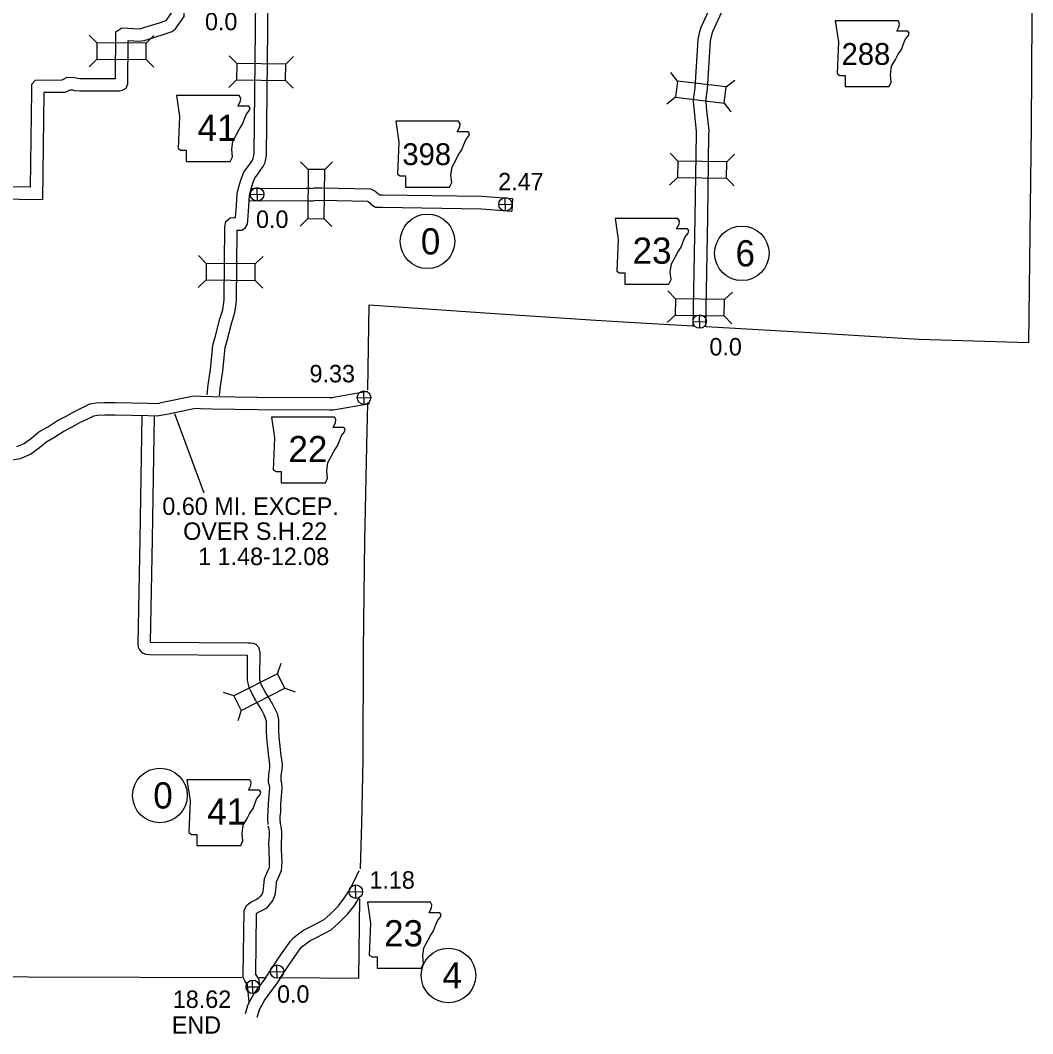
# Model space of a CAD drawing. Extents: x -939622 to -934245, y 1383184 to 1385301.
# Drawn here: x -936241.4 to -936167.9, y 1384497 to 1384570.6 of the extents above; entities that cross this region are included whole.
import ezdxf

# ---------------------------------------------------------------- set-up
doc = ezdxf.new("R2010")
doc.units = 0
for name, color, linetype in [('Level 10', 7, 'Continuous'), ('Level 2', 7, 'Continuous'), ('Level 20', 7, 'Continuous'), ('Level 21', 7, 'Continuous'), ('Level 25', 7, 'Continuous'), ('Level 26', 7, 'Continuous'), ('Level 27', 7, 'Continuous')]:
    doc.layers.add(name, color=color, linetype=linetype)

msp = doc.modelspace()

# ---------------------------------------------------------------- linework, layer by layer
at = {"layer": 'Level 10'}
for points in [[(-936192.57, 1384548.379), (-936192.426, 1384556.309), (-936192.345, 1384562.392), (-936192.332, 1384562.573), (-936192.503, 1384564.235), (-936192.549, 1384564.725), (-936192.522, 1384565.044), (-936192.44, 1384565.717), (-936192.226, 1384569.222), (-936192.094, 1384569.796), (-936192.004, 1384570.12), (-936190.111, 1384574.267), (-936189.791, 1384574.975), (-936189.482, 1384575.491), (-936189.193, 1384575.881), (-936188.85, 1384576.217), (-936187.072, 1384577.94), (-936186.895, 1384578.191), (-936186.701, 1384578.477), (-936186.578, 1384578.75), (-936186.455, 1384579.037), (-936186.424, 1384579.288), (-936186.351, 1384579.71), (-936186.114, 1384581.082)], [(-936191.67, 1384548.363), (-936191.526, 1384556.295), (-936191.445, 1384562.355), (-936191.429, 1384562.588), (-936191.607, 1384564.324), (-936191.646, 1384564.729), (-936191.626, 1384564.951), (-936191.543, 1384565.635), (-936191.332, 1384569.092), (-936191.221, 1384569.575), (-936191.156, 1384569.811), (-936189.292, 1384573.894), (-936188.992, 1384574.557), (-936188.733, 1384574.991), (-936188.513, 1384575.287), (-936188.222, 1384575.572), (-936186.385, 1384577.352), (-936186.155, 1384577.679), (-936185.912, 1384578.037), (-936185.754, 1384578.389), (-936185.578, 1384578.799), (-936185.533, 1384579.155), (-936185.464, 1384579.556), (-936185.227, 1384580.929)], [(-936240.303, 1384566.283), (-936238.366, 1384566.303), (-936238.286, 1384566.34), (-936238.002, 1384566.484), (-936237.455, 1384566.471), (-936237.275, 1384566.408), (-936237.092, 1384566.397), (-936236.707, 1384566.395), (-936234.498, 1384566.389), (-936234.485, 1384569.777), (-936234.058, 1384570.069), (-936233.602, 1384570.059), (-936232.794, 1384570), (-936232.64, 1384570.024), (-936232.442, 1384570.087), (-936231.246, 1384570.458), (-936230.822, 1384570.609), (-936230.802, 1384570.624), (-936230.41, 1384571.192), (-936230.353, 1384572.883)], [(-936227.862, 1384543.422), (-936227.771, 1384544.166), (-936227.613, 1384545.261), (-936227.524, 1384546.227), (-936227.435, 1384547.038), (-936227.275, 1384547.615), (-936226.935, 1384548.938), (-936226.72, 1384549.608), (-936226.635, 1384550.129), (-936226.621, 1384550.33), (-936226.563, 1384555.629), (-936226.505, 1384556.015), (-936226.18, 1384556.268), (-936225.926, 1384556.296), (-936225.801, 1384556.294), (-936225.734, 1384557.165), (-936225.676, 1384558.063), (-936225.526, 1384558.622), (-936225.392, 1384559.094), (-936225.183, 1384559.602), (-936224.908, 1384559.97), (-936224.719, 1384560.244), (-936224.563, 1384560.473), (-936224.503, 1384560.584), (-936224.448, 1384560.915), (-936224.325, 1384572.222)], [(-936226.963, 1384543.357), (-936226.879, 1384544.047), (-936226.719, 1384545.155), (-936226.628, 1384546.137), (-936226.548, 1384546.867), (-936226.405, 1384547.382), (-936226.07, 1384548.689), (-936225.843, 1384549.396), (-936225.74, 1384550.025), (-936225.721, 1384550.293), (-936225.665, 1384555.392), (-936225.33, 1384555.386), (-936225.09, 1384555.558), (-936224.923, 1384555.824), (-936224.913, 1384556.097), (-936224.837, 1384557.101), (-936224.783, 1384557.916), (-936224.659, 1384558.382), (-936224.54, 1384558.798), (-936224.394, 1384559.155), (-936224.177, 1384559.445), (-936223.976, 1384559.736), (-936223.794, 1384560.005), (-936223.64, 1384560.288), (-936223.549, 1384560.836), (-936223.425, 1384572.217)], [(-936239.716, 1384565.389), (-936238.163, 1384565.405), (-936237.892, 1384565.53), (-936237.796, 1384565.579), (-936237.618, 1384565.575), (-936237.455, 1384565.518), (-936237.122, 1384565.497), (-936236.71, 1384565.495), (-936234.191, 1384565.489), (-936234.017, 1384565.543), (-936233.743, 1384565.682), (-936233.6, 1384566.006), (-936233.587, 1384569.156), (-936232.757, 1384569.095), (-936232.432, 1384569.145), (-936232.172, 1384569.229), (-936230.962, 1384569.604), (-936230.388, 1384569.808), (-936230.142, 1384569.995), (-936229.519, 1384570.898), (-936229.484, 1384571.946)], [(-936240.303, 1384566.283), (-936240.596, 1384565.961), (-936240.614, 1384565.479), (-936240.704, 1384558.507), (-936248.42, 1384558.598), (-936253.269, 1384558.631)], [(-936239.716, 1384565.384), (-936239.816, 1384557.596), (-936248.429, 1384557.698), (-936253.276, 1384557.731)], [(-936224.612, 1384558.427), (-936224.067, 1384558.416), (-936220.672, 1384558.433), (-936220.333, 1384558.423), (-936220.245, 1384558.413), (-936220.084, 1384558.451), (-936219.804, 1384558.449), (-936219.549, 1384558.45), (-936216.01, 1384558.376), (-936215.663, 1384558.215), (-936215.424, 1384558.012), (-936215.383, 1384557.969), (-936215.365, 1384557.957), (-936215.144, 1384557.957), (-936207.908, 1384557.84), (-936205.682, 1384557.672), (-936205.749, 1384556.774)], [(-936224.77, 1384557.53), (-936224.074, 1384557.516), (-936220.683, 1384557.533), (-936220.393, 1384557.524), (-936220.188, 1384557.503), (-936219.984, 1384557.55), (-936219.804, 1384557.548), (-936219.556, 1384557.55), (-936216.217, 1384557.48), (-936216.153, 1384557.45), (-936216.045, 1384557.359), (-936215.964, 1384557.273), (-936215.63, 1384557.057), (-936215.151, 1384557.057), (-936207.949, 1384556.94), (-936205.749, 1384556.774)], [(-936241.655, 1384539.668), (-936241.131, 1384539.908), (-936240.582, 1384540.305), (-936240.07, 1384540.746), (-936239.45, 1384541.094), (-936238.706, 1384541.568), (-936238.079, 1384541.89), (-936237.523, 1384542.207), (-936236.912, 1384542.5), (-936236.365, 1384542.784), (-936235.901, 1384542.853), (-936235.296, 1384542.88), (-936234.541, 1384542.87), (-936232.136, 1384542.823), (-936231.562, 1384542.8), (-936231.364, 1384542.829), (-936230.977, 1384542.912), (-936228.944, 1384543.33), (-936228.644, 1384543.354), (-936228.302, 1384543.331), (-936227.468, 1384543.32), (-936224.199, 1384543.254), (-936219.006, 1384543.241), (-936218.778, 1384543.247), (-936218.425, 1384543.298), (-936216.203, 1384543.691)], [(-936242.279, 1384538.658), (-936241.392, 1384538.799), (-936240.675, 1384539.127), (-936240.024, 1384539.599), (-936239.552, 1384540.005), (-936238.987, 1384540.321), (-936238.257, 1384540.786), (-936237.65, 1384541.099), (-936237.104, 1384541.409), (-936236.51, 1384541.695), (-936236.084, 1384541.916), (-936235.814, 1384541.956), (-936235.282, 1384541.98), (-936234.557, 1384541.97), (-936232.163, 1384541.923), (-936231.514, 1384541.897), (-936231.204, 1384541.943), (-936230.792, 1384542.031), (-936228.816, 1384542.437), (-936228.638, 1384542.451), (-936228.338, 1384542.432), (-936227.483, 1384542.42), (-936224.209, 1384542.354), (-936218.994, 1384542.341), (-936218.701, 1384542.349), (-936218.283, 1384542.409), (-936216.046, 1384542.805)], [(-936232.605, 1384541.932), (-936232.644, 1384538.957), (-936232.747, 1384532.938), (-936232.885, 1384525.35), (-936232.868, 1384525.111), (-936232.755, 1384524.924), (-936232.606, 1384524.733), (-936232.334, 1384524.61), (-936232.033, 1384524.581), (-936224.939, 1384524.52), (-936224.961, 1384522.932), (-936224.957, 1384522.817), (-936224.946, 1384522.692), (-936224.932, 1384522.603), (-936224.912, 1384522.498), (-936224.888, 1384522.392), (-936224.859, 1384522.295), (-936224.823, 1384522.183), (-936224.788, 1384522.086), (-936224.736, 1384521.98), (-936224.501, 1384521.54), (-936224.436, 1384521.41), (-936224.354, 1384521.261), (-936224.261, 1384521.113), (-936224.054, 1384520.787), (-936223.967, 1384520.645), (-936223.929, 1384520.58), (-936223.893, 1384520.512)], [(-936231.706, 1384541.869), (-936231.744, 1384538.944), (-936231.847, 1384532.922), (-936231.983, 1384525.481), (-936224.912, 1384525.42), (-936224.717, 1384525.427), (-936224.524, 1384525.401), (-936224.326, 1384525.327), (-936224.131, 1384525.102), (-936224.045, 1384524.856), (-936224.036, 1384524.709), (-936224.061, 1384522.942), (-936224.058, 1384522.871), (-936224.052, 1384522.8), (-936224.046, 1384522.759), (-936224.031, 1384522.684), (-936224.016, 1384522.619), (-936223.999, 1384522.558), (-936223.972, 1384522.474), (-936223.959, 1384522.439), (-936223.934, 1384522.388), (-936223.702, 1384521.953), (-936223.64, 1384521.829), (-936223.579, 1384521.718), (-936223.5, 1384521.593), (-936223.291, 1384521.263), (-936223.197, 1384521.111), (-936223.144, 1384521.021), (-936223.097, 1384520.932)], [(-936223.097, 1384520.932), (-936222.943, 1384520.627), (-936222.771, 1384520.286), (-936222.683, 1384519.825), (-936222.665, 1384519.053), (-936222.648, 1384518.572), (-936222.5, 1384517.258), (-936222.414, 1384516.626), (-936222.439, 1384516.218), (-936222.511, 1384515.8), (-936222.518, 1384515.428), (-936222.469, 1384515.253), (-936222.427, 1384514.909), (-936222.45, 1384514.593), (-936222.527, 1384513.683), (-936222.541, 1384513.128), (-936222.574, 1384512.827), (-936222.574, 1384512.71), (-936222.557, 1384512.277)], [(-936223.893, 1384520.512), (-936223.747, 1384520.222), (-936223.632, 1384519.993), (-936223.581, 1384519.73), (-936223.565, 1384519.026), (-936223.546, 1384518.505), (-936223.393, 1384517.147), (-936223.318, 1384516.593), (-936223.335, 1384516.321), (-936223.409, 1384515.885), (-936223.42, 1384515.313), (-936223.354, 1384515.077), (-936223.331, 1384514.887), (-936223.347, 1384514.662), (-936223.426, 1384513.732), (-936223.44, 1384513.188), (-936223.474, 1384512.876), (-936223.474, 1384512.692), (-936223.456, 1384512.241)], [(-936223.441, 1384512.141), (-936223.382, 1384511.925), (-936223.351, 1384511.679), (-936223.353, 1384511.428), (-936223.394, 1384510.915), (-936223.372, 1384510.365), (-936223.344, 1384509.517), (-936223.352, 1384509.214), (-936223.359, 1384509.104), (-936223.453, 1384508.902), (-936223.718, 1384508.286), (-936223.74, 1384508.025), (-936223.778, 1384507.591), (-936223.816, 1384507.344), (-936223.871, 1384507.204), (-936224.042, 1384506.989), (-936224.143, 1384506.87), (-936224.275, 1384506.793), (-936224.604, 1384506.634), (-936224.865, 1384506.46), (-936225.025, 1384506.306), (-936225.184, 1384506.003), (-936225.253, 1384501.336), (-936225.257, 1384501.18)], [(-936222.572, 1384512.377), (-936222.497, 1384512.1), (-936222.45, 1384511.731), (-936222.454, 1384511.388), (-936222.493, 1384510.897), (-936222.473, 1384510.398), (-936222.444, 1384509.521), (-936222.453, 1384509.175), (-936222.471, 1384508.877), (-936222.632, 1384508.534), (-936222.834, 1384508.064), (-936222.844, 1384507.947), (-936222.884, 1384507.483), (-936222.942, 1384507.109), (-936223.083, 1384506.749), (-936223.346, 1384506.418), (-936223.555, 1384506.172), (-936223.851, 1384505.998), (-936224.157, 1384505.85), (-936224.287, 1384505.764), (-936224.352, 1384501.392)], [(-936223.603, 1384501.124), (-936222.621, 1384502.618), (-936221.81, 1384503.766), (-936221.573, 1384504.046), (-936221.318, 1384504.237), (-936220.85, 1384504.559), (-936220.329, 1384504.823), (-936219.825, 1384505.095), (-936219.367, 1384505.331), (-936218.924, 1384505.741), (-936218.323, 1384506.344), (-936217.901, 1384506.879), (-936217.53, 1384507.475), (-936217.191, 1384508.115), (-936216.816, 1384508.903)], [(-936222.499, 1384501.166), (-936221.877, 1384502.111), (-936221.098, 1384503.214), (-936220.952, 1384503.387), (-936220.793, 1384503.506), (-936220.39, 1384503.783), (-936219.912, 1384504.026), (-936219.405, 1384504.299), (-936218.846, 1384504.588), (-936218.3, 1384505.093), (-936217.649, 1384505.745), (-936217.163, 1384506.361), (-936216.812, 1384506.925)], [(-936224.029, 1384500.57), (-936224.045, 1384500.737), (-936224.088, 1384500.95), (-936224.141, 1384501.101), (-936224.352, 1384501.392)], [(-936224.816, 1384499.349), (-936224.936, 1384500.603), (-936224.952, 1384500.681), (-936224.989, 1384500.715), (-936225.119, 1384500.887), (-936225.257, 1384501.18)], [(-936223.603, 1384501.124), (-936224.425, 1384500.031), (-936224.594, 1384499.724), (-936224.792, 1384499.39), (-936224.929, 1384499.085), (-936225.104, 1384498.497)], [(-936222.499, 1384501.166), (-936222.721, 1384500.829), (-936223.665, 1384499.545), (-936223.813, 1384499.278), (-936223.992, 1384498.975), (-936224.084, 1384498.77), (-936224.241, 1384498.24)]]:
    msp.add_lwpolyline(points, dxfattribs=at)
at = {"layer": 'Level 2'}
for points in [[(-936191.637, 1384548.388), (-936184.086, 1384547.961), (-936176.198, 1384547.476), (-936168.21, 1384547.235), (-936168.129, 1384555.108), (-936168.033, 1384562.891), (-936167.971, 1384570.876), (-936167.936, 1384573.889)], [(-936216.185, 1384543.783), (-936216.091, 1384549.955), (-936208.041, 1384549.415), (-936200.041, 1384548.882), (-936197.253, 1384548.705)], [(-936197.253, 1384548.705), (-936192.59, 1384548.442)], [(-936216.628, 1384512.331), (-936216.542, 1384516.953), (-936216.499, 1384524.936), (-936216.407, 1384532.863), (-936216.229, 1384540.842), (-936216.2, 1384542.769)], [(-936216.733, 1384509.01), (-936216.733, 1384509.018), (-936216.628, 1384512.331)], [(-936222.469, 1384501.121), (-936216.846, 1384501.072), (-936216.764, 1384506.858)], [(-936245.302, 1384501.288), (-936240.826, 1384501.184), (-936232.764, 1384501.166), (-936225.326, 1384501.136)], [(-936224.068, 1384501.131), (-936223.692, 1384501.13)]]:
    msp.add_lwpolyline(points, dxfattribs=at)
at = {"layer": 'Level 20'}
for p, q in [((-936235.85, 1384568.982), (-936236.408, 1384569.544)), ((-936232.286, 1384568.967), (-936231.724, 1384569.525)), ((-936235.855, 1384567.794), (-936236.418, 1384567.236)), ((-936232.291, 1384567.779), (-936231.734, 1384567.217)), ((-936225.709, 1384567.476), (-936226.262, 1384568.043)), ((-936222.145, 1384567.437), (-936221.579, 1384567.991)), ((-936225.722, 1384566.289), (-936226.288, 1384565.735)), ((-936222.158, 1384566.25), (-936221.604, 1384565.683)), ((-936193.722, 1384566.208), (-936194.21, 1384566.832)), ((-936190.184, 1384565.777), (-936189.56, 1384566.266)), ((-936193.865, 1384565.029), (-936194.489, 1384564.54)), ((-936190.328, 1384564.598), (-936189.839, 1384563.974)), ((-936220.512, 1384559.786), (-936221.068, 1384560.35)), ((-936219.324, 1384559.777), (-936218.76, 1384560.332)), ((-936193.704, 1384560.397), (-936194.256, 1384560.965)), ((-936190.14, 1384560.349), (-936189.573, 1384560.902)), ((-936193.72, 1384559.209), (-936194.287, 1384558.657)), ((-936190.156, 1384559.162), (-936189.603, 1384558.594)), ((-936220.54, 1384556.222), (-936221.104, 1384555.667)), ((-936219.352, 1384556.213), (-936218.796, 1384555.649)), ((-936227.924, 1384552.968), (-936228.478, 1384553.534)), ((-936224.36, 1384552.929), (-936223.794, 1384553.483)), ((-936227.937, 1384551.78), (-936228.503, 1384551.226)), ((-936224.373, 1384551.741), (-936223.819, 1384551.175)), ((-936193.865, 1384550.408), (-936194.415, 1384550.978)), ((-936190.302, 1384550.344), (-936189.732, 1384550.894)), ((-936193.887, 1384549.221), (-936194.457, 1384548.671)), ((-936190.323, 1384549.156), (-936189.773, 1384548.586)), ((-936222.74, 1384523.187), (-936222.492, 1384523.939)), ((-936222.206, 1384522.126), (-936221.454, 1384521.878)), ((-936225.923, 1384521.583), (-936226.675, 1384521.832)), ((-936225.389, 1384520.522), (-936225.637, 1384519.77))]:
    msp.add_line(p, q, dxfattribs=at)
for points in [[(-936235.855, 1384567.794), (-936232.291, 1384567.779), (-936232.286, 1384568.967), (-936235.85, 1384568.982)], [(-936225.722, 1384566.289), (-936222.158, 1384566.25), (-936222.145, 1384567.437), (-936225.709, 1384567.476)], [(-936193.865, 1384565.029), (-936190.328, 1384564.598), (-936190.184, 1384565.777), (-936193.722, 1384566.208)], [(-936193.72, 1384559.209), (-936190.156, 1384559.162), (-936190.14, 1384560.349), (-936193.704, 1384560.397)], [(-936219.352, 1384556.213), (-936219.324, 1384559.777), (-936220.512, 1384559.786), (-936220.54, 1384556.222)], [(-936224.36, 1384552.929), (-936227.924, 1384552.968), (-936227.937, 1384551.78), (-936224.373, 1384551.741)], [(-936190.302, 1384550.344), (-936193.865, 1384550.408), (-936193.887, 1384549.221), (-936190.323, 1384549.156)], [(-936222.74, 1384523.187), (-936225.923, 1384521.583), (-936225.389, 1384520.522), (-936222.206, 1384522.126)]]:
    msp.add_lwpolyline(points, close=True, dxfattribs=at)
at = {"layer": 'Level 21'}
for points in [[(-936182.264, 1384570.579), (-936182.036, 1384569.056), (-936182.137, 1384566.747), (-936181.934, 1384566.62), (-936181.554, 1384566.62), (-936181.554, 1384565.808), (-936178.356, 1384565.808), (-936178.204, 1384566.138), (-936178.255, 1384566.671), (-936178.178, 1384567.28), (-936177.899, 1384567.762), (-936177.722, 1384568.117), (-936177.468, 1384568.498), (-936177.316, 1384568.904), (-936177.189, 1384569.234), (-936176.96, 1384569.513), (-936176.91, 1384569.691), (-936177.011, 1384569.818), (-936177.798, 1384569.818), (-936177.62, 1384570.173), (-936177.595, 1384570.401), (-936177.7, 1384570.577)], [(-936230.083, 1384565.15), (-936229.855, 1384563.627), (-936229.956, 1384561.318), (-936229.753, 1384561.191), (-936229.372, 1384561.191), (-936229.372, 1384560.379), (-936226.175, 1384560.379), (-936226.023, 1384560.709), (-936226.073, 1384561.242), (-936225.997, 1384561.851), (-936225.718, 1384562.333), (-936225.54, 1384562.689), (-936225.287, 1384563.069), (-936225.134, 1384563.475), (-936225.008, 1384563.805), (-936224.779, 1384564.084), (-936224.728, 1384564.262), (-936224.83, 1384564.389), (-936225.617, 1384564.389), (-936225.439, 1384564.744), (-936225.414, 1384564.972), (-936225.519, 1384565.148)], [(-936214.166, 1384563.287), (-936213.938, 1384561.765), (-936214.039, 1384559.455), (-936213.836, 1384559.328), (-936213.456, 1384559.328), (-936213.456, 1384558.516), (-936210.258, 1384558.516), (-936210.106, 1384558.846), (-936210.157, 1384559.379), (-936210.08, 1384559.988), (-936209.801, 1384560.47), (-936209.624, 1384560.826), (-936209.37, 1384561.206), (-936209.218, 1384561.612), (-936209.091, 1384561.942), (-936208.862, 1384562.221), (-936208.812, 1384562.399), (-936208.913, 1384562.526), (-936209.7, 1384562.526), (-936209.522, 1384562.881), (-936209.497, 1384563.11), (-936209.602, 1384563.285)], [(-936198.247, 1384556.236), (-936198.019, 1384554.714), (-936198.12, 1384552.404), (-936197.917, 1384552.278), (-936197.537, 1384552.278), (-936197.537, 1384551.465), (-936194.339, 1384551.465), (-936194.187, 1384551.795), (-936194.238, 1384552.328), (-936194.161, 1384552.937), (-936193.882, 1384553.419), (-936193.705, 1384553.775), (-936193.451, 1384554.155), (-936193.299, 1384554.561), (-936193.172, 1384554.891), (-936192.943, 1384555.17), (-936192.893, 1384555.348), (-936192.994, 1384555.475), (-936193.781, 1384555.475), (-936193.603, 1384555.83), (-936193.578, 1384556.059), (-936193.683, 1384556.234)], [(-936223.182, 1384541.819), (-936222.954, 1384540.297), (-936223.055, 1384537.987), (-936222.852, 1384537.861), (-936222.471, 1384537.861), (-936222.471, 1384537.049), (-936219.274, 1384537.049), (-936219.122, 1384537.378), (-936219.172, 1384537.911), (-936219.096, 1384538.52), (-936218.817, 1384539.003), (-936218.639, 1384539.358), (-936218.386, 1384539.738), (-936218.233, 1384540.145), (-936218.107, 1384540.474), (-936217.878, 1384540.754), (-936217.827, 1384540.931), (-936217.929, 1384541.058), (-936218.716, 1384541.058), (-936218.538, 1384541.413), (-936218.513, 1384541.642), (-936218.618, 1384541.817)], [(-936229.318, 1384515.482), (-936229.09, 1384513.96), (-936229.191, 1384511.65), (-936228.988, 1384511.523), (-936228.608, 1384511.523), (-936228.608, 1384510.711), (-936225.41, 1384510.711), (-936225.258, 1384511.041), (-936225.309, 1384511.574), (-936225.233, 1384512.183), (-936224.954, 1384512.665), (-936224.776, 1384513.021), (-936224.522, 1384513.401), (-936224.37, 1384513.807), (-936224.243, 1384514.137), (-936224.015, 1384514.416), (-936223.964, 1384514.594), (-936224.065, 1384514.721), (-936224.852, 1384514.721), (-936224.674, 1384515.076), (-936224.649, 1384515.305), (-936224.754, 1384515.48)], [(-936216.218, 1384506.591), (-936215.989, 1384505.068), (-936216.091, 1384502.759), (-936215.888, 1384502.632), (-936215.507, 1384502.632), (-936215.507, 1384501.82), (-936212.31, 1384501.82), (-936212.158, 1384502.15), (-936212.208, 1384502.683), (-936212.132, 1384503.292), (-936211.853, 1384503.774), (-936211.675, 1384504.129), (-936211.422, 1384504.51), (-936211.269, 1384504.916), (-936211.142, 1384505.246), (-936210.914, 1384505.525), (-936210.863, 1384505.703), (-936210.965, 1384505.829), (-936211.752, 1384505.829), (-936211.574, 1384506.185), (-936211.549, 1384506.413), (-936211.654, 1384506.589)]]:
    msp.add_lwpolyline(points, close=True, dxfattribs=at)
at = {"layer": 'Level 25'}
msp.add_line((-936230.218, 1384542.073), (-936228.083, 1384536.316), dxfattribs=at)
at = {"layer": 'Level 26'}
for p, q in [((-936224.21, 1384557.497), (-936224.233, 1384558.474)), ((-936224.71, 1384557.974), (-936223.733, 1384557.997)), ((-936206.195, 1384556.774), (-936206.217, 1384557.751)), ((-936206.694, 1384557.251), (-936205.718, 1384557.274)), ((-936192.093, 1384548.258), (-936192.115, 1384549.235)), ((-936192.592, 1384548.735), (-936191.616, 1384548.758)), ((-936216.461, 1384542.739), (-936216.483, 1384543.715)), ((-936216.96, 1384543.216), (-936215.984, 1384543.238)), ((-936217.553, 1384507.348), (-936216.577, 1384507.37)), ((-936217.054, 1384506.871), (-936217.076, 1384507.847)), ((-936223.266, 1384501.55), (-936222.29, 1384501.573)), ((-936222.767, 1384501.073), (-936222.789, 1384502.05)), ((-936224.53, 1384499.967), (-936224.552, 1384500.943)), ((-936225.029, 1384500.444), (-936224.053, 1384500.466))]:
    msp.add_line(p, q, dxfattribs=at)
for centre in [(-936224.222, 1384557.985), (-936206.206, 1384557.262), (-936192.104, 1384548.746), (-936216.472, 1384543.227), (-936217.065, 1384507.359), (-936222.778, 1384501.561), (-936224.541, 1384500.455)]:
    msp.add_circle(centre, 0.488, dxfattribs=at)
at = {"layer": 'Level 27'}
for centre in [(-936211.862, 1384554.571), (-936189.047, 1384553.705), (-936231.28, 1384514.347), (-936210.344, 1384501.284)]:
    msp.add_circle(centre, 1.98, dxfattribs=at)

# ---------------------------------------------------------------- texts
at = {"layer": 'Level 21'}
for s, height, p in [('288', 1.584, (-936181.808, 1384567.382)), ('41', 1.9008, (-936228.557, 1384561.857)), ('398', 1.584, (-936213.684, 1384560.107)), ('23', 1.9008, (-936196.979, 1384552.946)), ('22', 1.9008, (-936221.957, 1384538.542)), ('41', 1.9008, (-936227.848, 1384512.236)), ('23', 1.9008, (-936215.012, 1384503.391))]:
    msp.add_text(s, height=height, dxfattribs=at).set_placement(p)
at = {"layer": 'Level 25'}
for s, p in [('0.0', (-936228.012, 1384569.894)), ('2.47', (-936206.732, 1384558.275)), ('0.0', (-936224.307, 1384555.544)), ('0.0', (-936191.402, 1384546.288)), ('9.33', (-936220.423, 1384544.337)), ('0.60 MI. EXCEP.', (-936231.106, 1384534.712)), ('OVER S.H.22', (-936229.595, 1384532.901)), ('1 1.48-12.08', (-936228.507, 1384531.069)), ('1.18', (-936216.079, 1384507.577)), ('18.62', (-936230.347, 1384498.921)), ('0.0', (-936222.784, 1384499.297)), ('END', (-936230.423, 1384497.05))]:
    msp.add_text(s, height=1.2672, dxfattribs=at).set_placement(p)
at = {"layer": 'Level 27'}
for s, p in [('0', (-936212.346, 1384553.621)), ('6', (-936189.507, 1384552.755)), ('0', (-936231.764, 1384513.397)), ('4', (-936210.77, 1384500.334))]:
    msp.add_text(s, height=1.901, dxfattribs=at).set_placement(p)

doc.saveas('drawing.dxf')
